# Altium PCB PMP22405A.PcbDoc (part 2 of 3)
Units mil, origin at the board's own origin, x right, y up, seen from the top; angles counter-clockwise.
Board outline 4300 x 4000 mil, 6 copper layers (Top Layer, Layer 2, Signal Layer 3, Signal Layer 4, Layer 5, Bottom Layer), stack 61.712 mil thick; 195 components, 65 nets, 472 pads, 772 vias.
Unrouted connection lines stored in the file: 12.
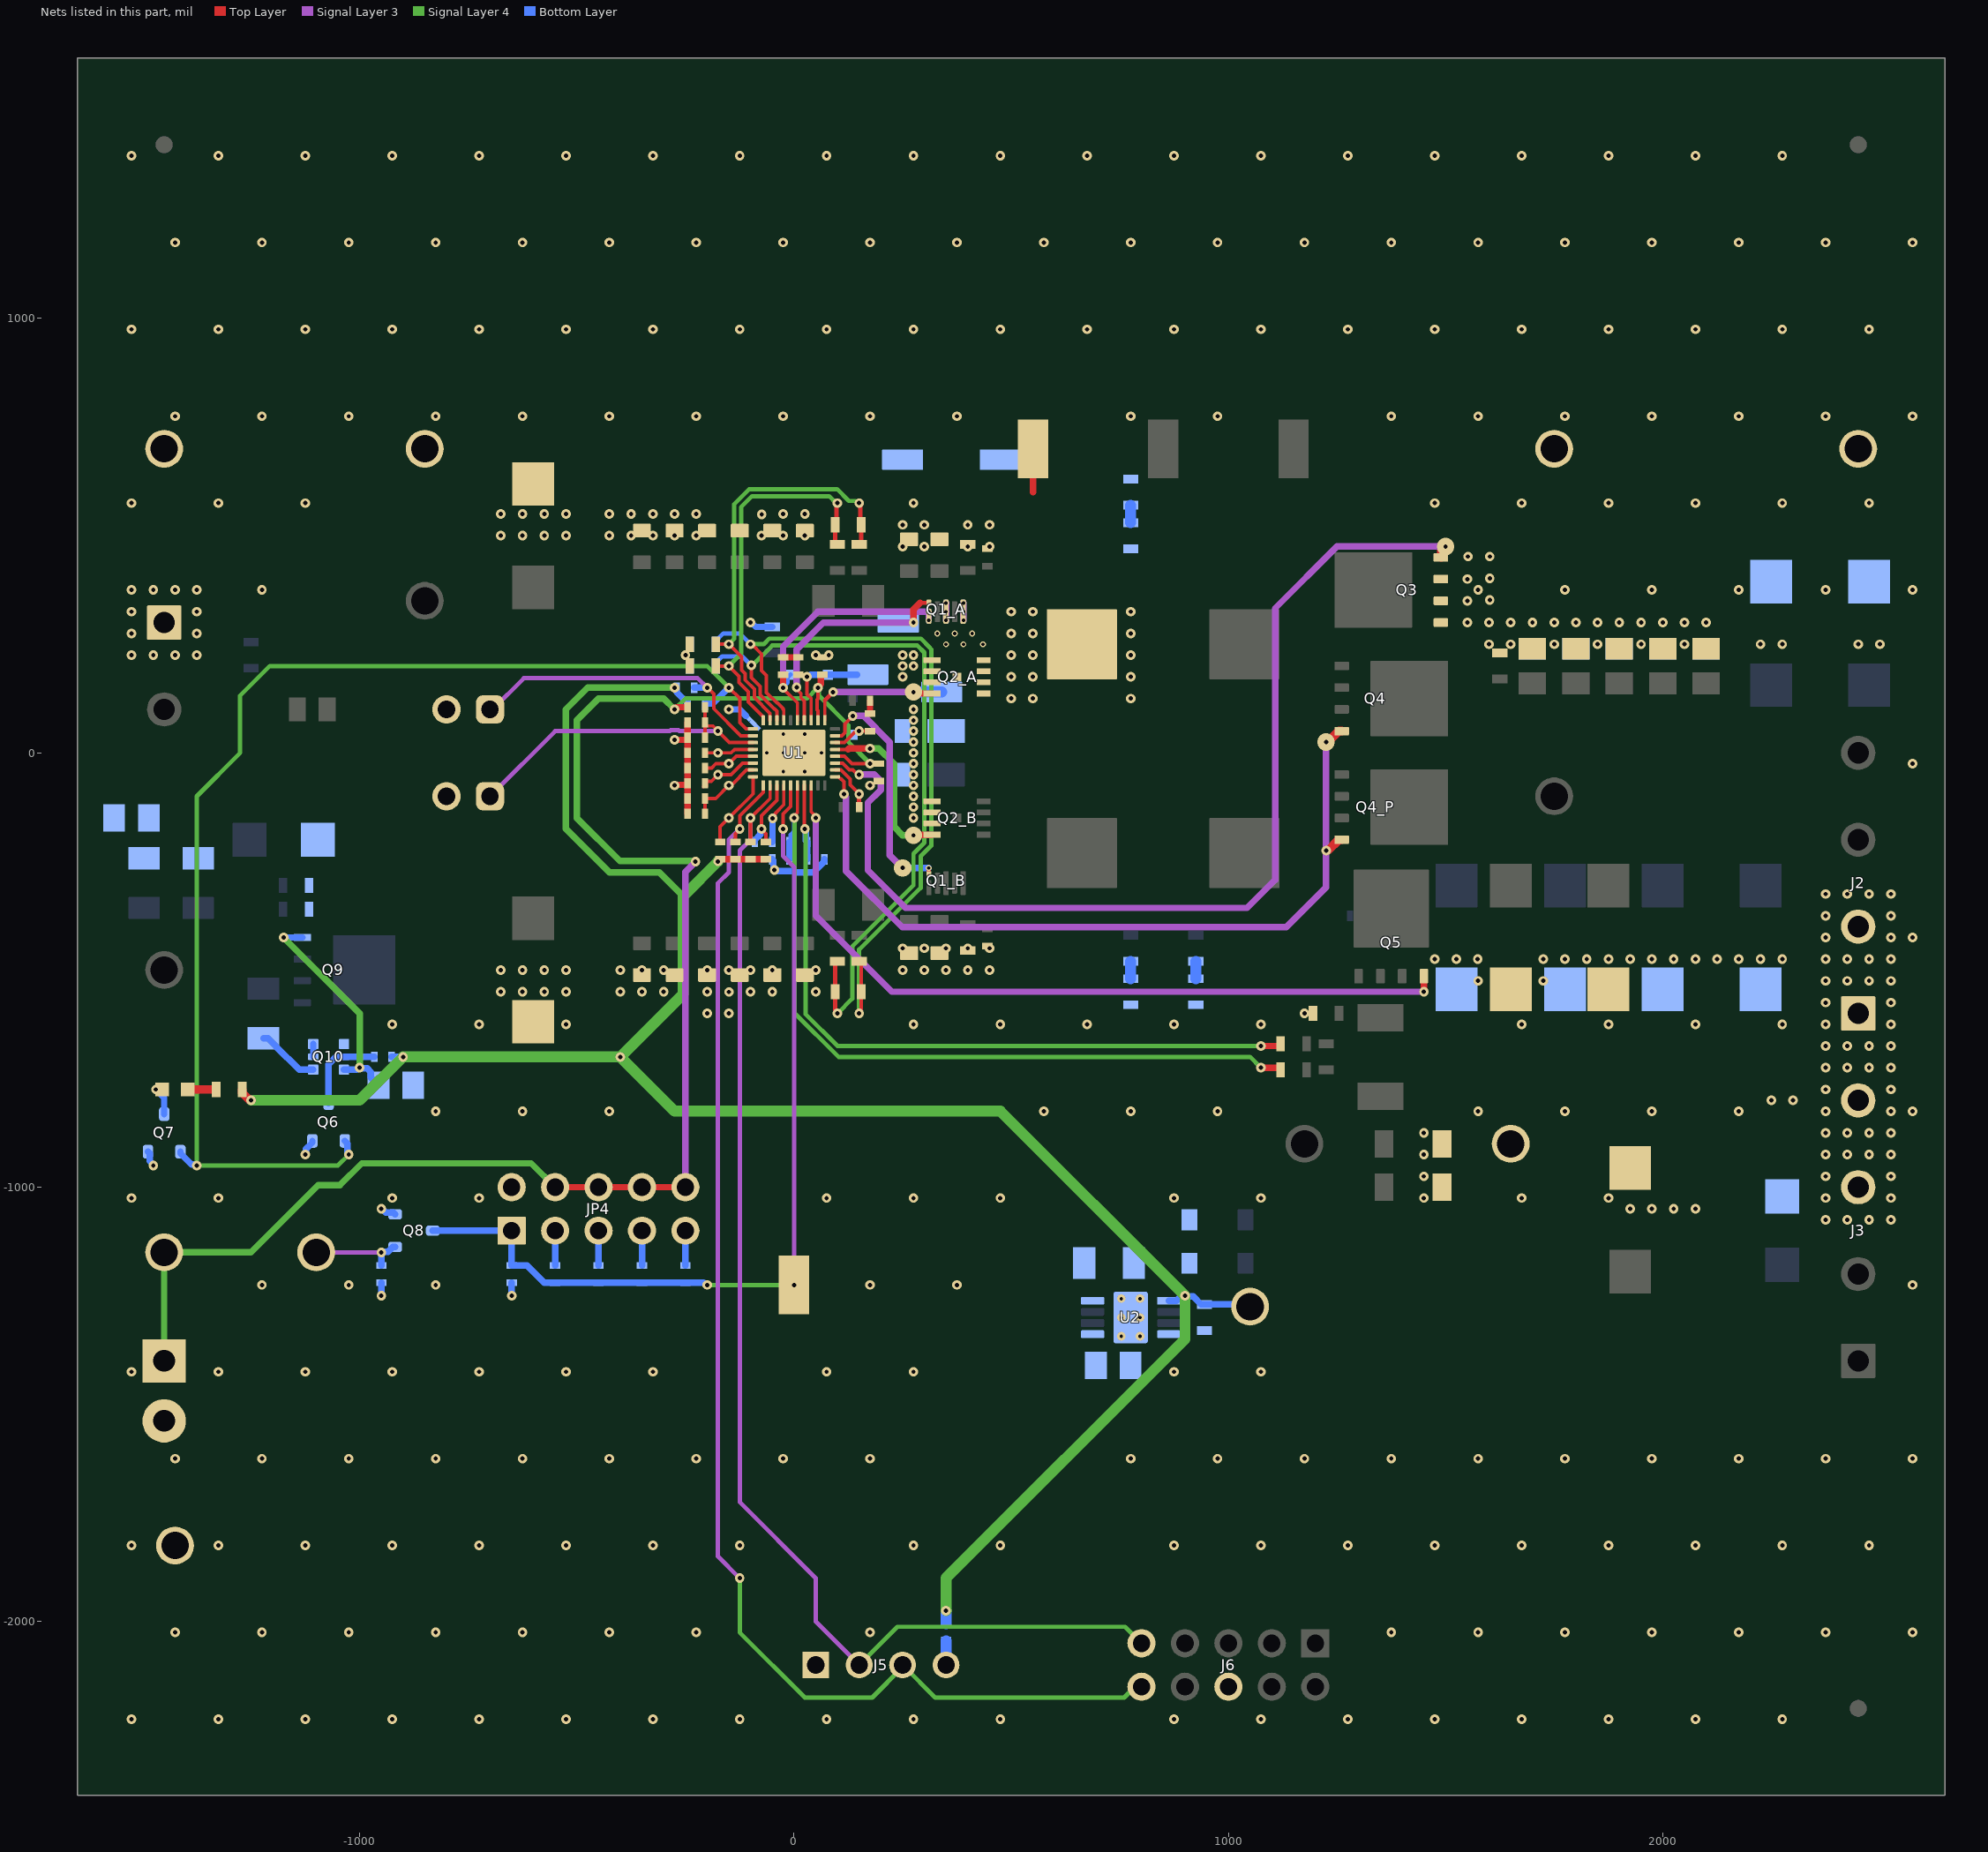
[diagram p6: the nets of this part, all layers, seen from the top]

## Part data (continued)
C51 C60 C62: library part CMP-0007449-4, "CAP, CERM, 330 pF, 50 V, +/- 10%, X7R, 0603", Cap_Case=0603, Manufacturer=MuRata, PartNumber=GRM188R71H331KA01D, Supplier Part Number 1=490-1486-1-ND, TempCo=X7R, Tolerance_%=10%, Value1=Unknown, Value2=50V, ValueDisplayed=330pF
C52: library part CMP-0077895-3, "CAP, CERM, 0.22 µF, 100 V,+/- 20%, X7S, AEC-Q200 Grade 1, 0603", Cap_Case=0603, Manufacturer="Taiyo Yuden", Supplier Part Number 1=587-5013-1-ND, TempCo=X7S, Tolerance_%=20%, Value2=100V, ValueDisplayed=0.22µF
C61 C72: library part CMP-0750059-1, "CAP, CERM, 1 µF, 100 V,+/- 10%, X7S, 0805", Cap_Case=0805, Manufacturer=TDK, TempCo=X7S, Tolerance_%=10%, Value2=100V, ValueDisplayed=1µF
C63 C65: library part CMP-0006681-2, "CAP, CERM, 0.018 uF, 50 V, +/- 10%, X7R, 0402", Cap_Case=0402, Manufacturer=MuRata, Supplier Part Number 1=GRM155R71H183KA12D-ND, TempCo=X7R, Tolerance_%=10%, Value1=Unknown, Value2=50V, ValueDisplayed=0.018uF
C64: library part CMP-0006331-2, "CAP, CERM, 0.068 uF, 50 V, +/- 10%, X7R, AEC-Q200 Grade 1, 0402", Cap_Case=0402, Manufacturer=TDK, Supplier Part Number 1=445-6898-1-ND, TempCo=X7R, Tolerance_%=10%, Value1="0.05606 ohm", Value2=50V, ValueDisplayed=0.068uF
C71: library part CMP-0007355-6, "CAP, CERM, 10 uF, 35 V, +/- 20%, X5R, 0603", Cap_Case=0603, Manufacturer=Murata, TempCo=X5R, Tolerance_%=20%, Value1=Unknown, Value2=35V, ValueDisplayed=10uF
D1: library part CMP-0002827-3, "LED, Green, SMD", Color=green, Manufacturer=Lite-On, PartNumber=LTST-C190GKT, Power_TotalModule=100mW, Value1=0.1W, Value2=2.1V
D2 D3: library part CMP-0005870-3, "Diode, Zener, 5.1 V, 400 mW, SOD-323F", Manufacturer="Diodes Inc.", Power_W=400mW, Value1=0.4W
D4 D5: library part CMP-0076948-2, "Diode, Schottky, 100 V, 2 A, PowerDI123", Manufacturer="Diodes Inc.", Value1=2A, Value2=0.86V
D6: library part CMP-0028403-2, "Diode, Schottky, 40 V, 2 A, SMA", Manufacturer="Diodes Inc.", Value1=2A, Value2=0.5V
D7 D8: library part CMP-0750148-1, "Diode, Switching, 100 V, 0.3 A, AEC-Q101, SOD-123", Manufacturer="Diodes Inc.", Value1=0.3A, Value2=1.25V
FID1 FID2 FID3 FID4 FID5 FID6: library part CMP-0077181-1, "Fiducial mark.  There is nothing to buy or mount.", Manufacturer=N/A
H3 H4 H5 H6: library part CMP-0003620-1, "Bumpon, Hemisphere, 0.44 X 0.20, Clear", Manufacturer=3M, PartNumber="SJ-5303 (CLEAR)", Supplier Part Number 1=SJ5303-7-ND
J1: library part CMP-0074910-1, "Terminal Block, 5.08 mm, 2x1, Brass, TH", Color=Blue, Current_A=15A, Manufacturer="On-Shore Technology", PartNumber=ED120/2DS, Supplier Part Number 1=ED1609-ND, Voltage_V=300V
J2 J3: library part CMP-0074939-1, "Terminal Block, 5.08 mm, 4x1, Brass, TH", Color=Blue, Current_A=15A, Manufacturer="On-Shore Technology", Supplier Part Number 1=ED2227-ND, Voltage_V=300V
J4: library part CMP-0074913-1, "Terminal Block, 3.5mm Pitch, 2x1, TH", Color=Grey, Current_A=6A, Manufacturer="On-Shore Technology", Supplier Part Number 1=ED1514-ND, Voltage_V=150V
J5: library part CMP-0089047-2, "Connector Header Through Hole, Right Angle 4 position 0.100\" (2.54mm)", Current_A=4A, Manufacturer=Molex, Voltage_V=500V
J6: library part CMP-0055448-2, "Header (shrouded), 100mil, 5x2, High-Temperature, Gold, TH", Manufacturer=3M, Supplier Part Number 1=MHC10K-ND
JP1 JP2: library part CMP-0075405-3, "Header, 100mil, 2x1, Gold, TH", Color=Black, Current_A=6.3A, Manufacturer=Samtec, Supplier Part Number 1=SAM1029-02-ND, Voltage_V=550V
JP4: library part CMP-0075410-2, "Header, 100mil, 5x2, Gold, TH", Color=Black, Current_A=6.3A, Manufacturer=Samtec, Supplier Part Number 1=SAM1028-05-ND, Voltage_V=550V
L1_A L1_B: library part CMP-0089738-2, "Fixed Inductor 4.7uH 20% 100kHz 15A 7.5mOhm", Manufacturer=Cyntec, Operating Temperature Range="-55°C to +125°C", Part Number=CMLE105T-4R7MS, Test Frequency=100kHz, Tolerance_%=20%
LBL1: library part CMP-0003625-1, "Thermal Transfer Printable Labels, 0.650\" W x 0.200\" H - 10,000 per roll", Manufacturer=Brady, Supplier Part Number 1=97C5133
LOGO2: library part CMP-0074837-2, "IEC 61010-1 Hot Surface Warning", Manufacturer="Texas Instruments"
Logo3: library part CMP-0074769-3, Manufacturer="Texas Instruments"
LOGO4: library part CMP-0074844-1
Logo5: library part CMP-0074847-1, "FCC_disclaimer"
NT1: library part CMP-0078142-6, "Single point connection between nets.", Manufacturer=N/A
Q1_A Q1_B: library part EPC2204, "100V 32A 6mE", Manufacturer=EPC, Supplier Part Number 1=917-1223-1-ND
Q2_A Q2_B: library part CMP-0084434-1, "MOSFET, N-CH, 80 V, 40 A, 8-PG-TSDSON", Alternate Manufacturer=None, Manufacturer="Infineon Technologies", Value1="0.0135 ohm", Value2="22 nC"
Q3 Q4 Q4_P Q5: library part CMP-0096418-1, "N-Channel 60 V 100A (Tc) 83W (Tc) Surface Mount PG-TDSON-8-7", Digikey Part Number=BSC027N06LS5ATMA1CT-ND, Drain To Source Breakdown Voltage=60V, Input Capacitace At Vds="3300pF @ 30V", Manufacturer=Infineon, Mouser Part Number=726-BSC027N06LS5ATMA, Operating Temperature Range="-55°C to +150°C", Power_W=2.5W, Pulse Drain Current=536A, Typ Forward Diode Voltage=0.8V
Q6 Q7 Q8: library part CMP-0000772-1, "MOSFET, N-CH, 60 V, 0.26 A, SOT-23", Alternate Manufacturer=None, Manufacturer="ON Semiconductor", PartNumber=2N7002ET1G, Supplier Part Number 1=2N7002ET1GOSCT-ND, Value2="0.81 nC"
Q9: library part CMP-0000142-3, "MOSFET, P-CH, -80 V, -32 A, AEC-Q101, PowerPAK_SO-8L", Alternate Manufacturer=None, Manufacturer=Vishay-Siliconix, Value2="101 nC"
Q10: library part CMP-0121666-1, "Pre-Biased Bipolar Transistor (BJT) 1 NPN, 1 PNP - Pre-Biased (Dual) 80V 100mA 170MHz, 150MHz 350mW Surface Mount 6-TSSOP", Collector Base Voltage=80V, Digikey Part Number=1727-NHUMD12XCT-ND, Emitter Base Voltage=10V, Manufacturer=Nexperia, Mouser Part Number=771-NHUMD12X, Operating Temperature Range="to +150°C", Power_W=350mW, Unity Gain Freq=170/150MHz
R1 R2 R15 R16: library part CMP-0022478-4, "RES, 4.99, 1%, 0.1 W, AEC-Q200 Grade 0, 0603", Manufacturer=Vishay-Dale, PartNumber=CRCW06034R99FKEA, Power_W=100mW, Supplier Part Number 1=541-4.99HHCT-ND, TempCo="100 ppm/C", Tolerance_%=1%, Value2=0.1W, Value_Code=4R99, ValueDisplayed=4.99
R3 R6: library part CMP-0026866-3, "RES, 1.0, 5%, 0.063 W, AEC-Q200 Grade 0, 0402", Manufacturer=Vishay-Dale, Power_W=63mW, Supplier Part Number 1=541-1.0JCT-ND, TempCo="200 ppm/C", Tolerance_%=5%, Value2=0.063W, Value_Code=1R00, ValueDisplayed=1.0
R4: library part CMP-0020833-2, "RES, 0, 1%, 0.5 W, 0805", Manufacturer=Keystone, Power_W=500mW, Supplier Part Number 1=36-5106CT-ND, TempCo=ppm/C, Tolerance_%=1%, Value2=0.5W, Value_Code=0
R5: library part CMP-0026158-2, "RES, 200 k, 1%, 0.063 W, AEC-Q200 Grade 0, 0402", Manufacturer=Vishay-Dale, Power_W=63mW, Supplier Part Number 1=541-200KLCT-ND, TempCo="100 ppm/C", Tolerance_%=1%, Value2=0.063W, Value_Code=200k
R7 R26: library part CMP-0026279-2, "RES, 300 k, 1%, 0.063 W, AEC-Q200 Grade 0, 0402", Manufacturer=Vishay-Dale, Power_W=63mW, Supplier Part Number 1=541-300KLCT-ND, TempCo="100 ppm/C", Tolerance_%=1%, Value2=0.063W, Value_Code=300k
R8: library part CMP-0026336-2, "RES, 3.57 k, 1%, 0.063 W, AEC-Q200 Grade 0, 0402", Manufacturer=Vishay-Dale, Power_W=63mW, Supplier Part Number 1=541-3.57KLCT-ND, TempCo="100 ppm/C", Tolerance_%=1%, Value2=0.063W, Value_Code=3k57, ValueDisplayed=3.57k
R9: library part CMP-0026027-3, "RES, 15.0 k, 1%, 0.063 W, AEC-Q200 Grade 0, 0402", Manufacturer=Vishay-Dale, Power_W=63mW, Supplier Part Number 1=541-15.0KLCT-ND, TempCo="100 ppm/C", Tolerance_%=1%, Value2=0.063W, Value_Code=15k0, ValueDisplayed=15.0k
R10: library part CMP-0026744-1, "RES, 82.0 k, 1%, 0.063 W, 0402", Manufacturer="Yageo America", Power_W=63mW, Supplier Part Number 1=311-82.0KLRCT-ND, TempCo="100 ppm/C", Tolerance_%=1%, Value2=0.063W, Value_Code=82k0, ValueDisplayed=82.0k
R11 R12 R13 R14 R24 R48: library part CMP-0025958-3, "RES, 10.0 k, 1%, 0.063 W, AEC-Q200 Grade 0, 0402", Manufacturer=Vishay-Dale, Power_W=63mW, Supplier Part Number 1=541-10.0KLCT-ND, TempCo="100 ppm/C", Tolerance_%=1%, Value2=0.063W, Value_Code=10k0, ValueDisplayed=10.0k
R17 R18: library part CMP-0025703-4, "RES, 10, 5%, 0.1 W, AEC-Q200 Grade 0, 0603", Manufacturer=Vishay-Dale, PartNumber=CRCW060310R0JNEA, Power_W=100mW, Supplier Part Number 1=541-10GCT-ND, TempCo="200 ppm/C", Tolerance_%=5%, Value2=0.1W, Value_Code=10R0, ValueDisplayed=10
R19: library part CMP-0022268-4, "RES, 2.00 k, 1%, 0.1 W, AEC-Q200 Grade 0, 0603", Manufacturer=Vishay-Dale, PartNumber=CRCW06032K00FKEA, Power_W=100mW, Supplier Part Number 1=541-2.00KHCT-ND, TempCo="100 ppm/C", Tolerance_%=1%, Value2=0.1W, Value_Code=2k00, ValueDisplayed=2.00k
R21 R30 R32: library part CMP-0025829-4, "RES, 56, 5%, 0.1 W, AEC-Q200 Grade 0, 0603", Manufacturer=Vishay-Dale, PartNumber=CRCW060356R0JNEA, Power_W=100mW, Supplier Part Number 1=541-56GCT-ND, TempCo="200 ppm/C", Tolerance_%=5%, Value2=0.1W, Value_Code=56R0, ValueDisplayed=56
R23: library part CMP-0026021-3, "RES, 150 k, 1%, 0.063 W, AEC-Q200 Grade 0, 0402", Manufacturer=Vishay-Dale, Power_W=63mW, Supplier Part Number 1=541-150KLCT-ND, TempCo="100 ppm/C", Tolerance_%=1%, Value2=0.063W, Value_Code=150k
R25: library part CMP-0026721-1, "RES, 100 k, 1%, 0.0625 W, 0402", Manufacturer="Yageo America", Power_W=62.5mW, Supplier Part Number 1=311-100KLRCT-ND, TempCo="100 ppm/C", Tolerance_%=1%, Value2=0.0625W, Value_Code=100k
R27: library part CMP-0025958-3, "RES, 10.0 k, 1%, 0.063 W, AEC-Q200 Grade 0, 0402", Manufacturer=Vishay-Dale, PartNumber=CRCW040210K0FKED, Power_W=63mW, Supplier Part Number 1=541-10.0KLCT-ND, TempCo="100 ppm/C", Tolerance_%=1%, Value2=0.063W, Value_Code=10k0, ValueDisplayed=10.0k
R28: library part CMP-0078584-1, "RES, 33.0 k, 1%, 0.063 W, 0402", Manufacturer="Yageo America", Power_W=63mW, Supplier Part Number 1=311-33.0KLRCT-ND, TempCo="100 ppm/C", Tolerance_%=1%, Value2=0.063W, Value_Code=33k0, ValueDisplayed=33.0k
R29: library part CMP-0026071-3, "RES, 1.00 k, 1%, 0.063 W, AEC-Q200 Grade 0, 0402", Manufacturer=Vishay-Dale, Power_W=63mW, Supplier Part Number 1=541-1.00KLCT-ND, TempCo="100 ppm/C", Tolerance_%=1%, Value2=0.063W, Value_Code=1k00, ValueDisplayed=1.00k
R33: library part CMP-0026893-2, "RES, 2.0 M, 5%, 0.063 W, AEC-Q200 Grade 0, 0402", Manufacturer=Vishay-Dale, Power_W=63mW, Supplier Part Number 1=541-2.0MJCT-ND, TempCo="200 ppm/C", Tolerance_%=5%, Value2=0.063W, Value_Code=2M00, ValueDisplayed=2.0M
R34 R35: library part CMP-0018679-3, "RES, 3.9, 5%, 0.25 W, AEC-Q200 Grade 0, 1206", Manufacturer=Vishay-Dale, PartNumber=CRCW12063R90JNEA, Power_W=250mW, Supplier Part Number 1=541-3.9ECT-ND, TempCo="200 ppm/C", Tolerance_%=5%, Value2=0.25W, Value_Code=3R90
R44: library part CMP-0022735-5, "RES, 100 k, 1%, 0.1 W, 0603", Manufacturer=Yageo, Power_W=100mW, Supplier Part Number 1=311-100KHRCT-ND, TempCo="100 ppm/C", Tolerance_%=1%, Value2=0.1W, Value_Code=100k
R45: library part CMP-0026822-3, "RES, 0, 5%, 0.063 W, AEC-Q200 Grade 0, 0402", Manufacturer=Vishay-Dale, Power_W=63mW, Supplier Part Number 1=541-0.0JCT-ND, TempCo="200 ppm/C", Tolerance_%=5%, Value2=0.063W, Value_Code=0000, ValueDisplayed=0
R46 R50: library part CMP-0017299-3, "RES, 10.0, 1%, 0.25 W, AEC-Q200 Grade 0, 1206", Manufacturer=Panasonic, Power_W=250mW, Supplier Part Number 1=P10.0FCT-ND, TempCo="100 ppm/C", Tolerance_%=1%, Value2=0.25W, Value_Code=10R0, ValueDisplayed=10.0
R47: library part CMP-0025743-4, "RES, 1.0, 5%, 0.1 W, AEC-Q200 Grade 0, 0603", Manufacturer=Vishay-Dale, Power_W=100mW, Supplier Part Number 1=541-1.0GCT-ND, TempCo="200 ppm/C", Tolerance_%=5%, Value2=0.1W, Value_Code=1R00, ValueDisplayed=1.0
R49: library part CMP-0021042-3, "RES, 20.0 k, 1%, 0.125 W, AEC-Q200 Grade 0, 0805", Manufacturer=Vishay-Dale, Power_W=125mW, Supplier Part Number 1=541-20.0KCCT-ND, TempCo="100 ppm/C", Tolerance_%=1%, Value2=0.125W, Value_Code=20k0, ValueDisplayed=20.0k
R51: library part CMP-0092287-1, "100 ±5% 0.063W, 1/16W Chip Resistor 0402 (1005 Metric) Moisture Resistant Thick Film", Digikey Part Number=13-RC0402JR-13100RLTR-ND, Manufacturer=Yageo, Mouser Part Number=603-RC0402JR-13100RL, Operating Temperature Range="-55°C to +155°C", Power_W=63mW, TempCo=100ppm/°C, Tolerance_%=5%
RAC_A RAC_B: library part CMP-0018570-2, "RES, 0.01, 1%, 1 W, 1206", Manufacturer=Vishay-Dale, Power_W=1W, Supplier Part Number 1=WSLP-.01CT-ND, TempCo="75 ppm/C", Tolerance_%=1%, Value_Code=R010, ValueDisplayed=0.01
RSR: library part CMP-0016512-2, "RES, 0.005, 1%, 1.5 W, 2010", Manufacturer="Stackpole Electronics Inc", Power_W=1.5W, Supplier Part Number 1=CSNL2010FT5L00CT-ND, TempCo="50 ppm/C", Tolerance_%=1%, Value_Code=5L000, ValueDisplayed=0.005
SH-JP1 SH-JP2 SH-JP4: library part CMP-0003623-3, "Shunt, 100mil, Gold plated, Black", Alternate Manufacturer=3M, Alternate PartNumber=969102-0000-DA, Manufacturer=Samtec, Supplier Part Number 1=SAM8858-ND
TP1 TP22 TP23 TP24 TP29 TP31 TP32: library part CMP-0055147-2, "Test Point, Multipurpose, Red, TH", Color=Red, Manufacturer="Keystone Electronics", Supplier Part Number 1=36-5010-ND
TP2 TP3 TP4 TP11 TP40: library part CMP-0067620-1, "PC Test Point, SMT", Manufacturer="TE Connectivity", Supplier Part Number 1=A106145CT-ND
TP15 TP16 TP17 TP33: library part CMP-0055152-2, "Test Point, Miniature, SMT", Manufacturer="Keystone Electronics", Supplier Part Number 1=36-5015TR-ND
TP18 TP19 TP20 TP21 TP30 TP41: library part CMP-0055148-2, "Test Point, Multipurpose, Black, TH", Color=Black, Manufacturer="Keystone Electronics", Supplier Part Number 1=36-5011-ND
U1: library part CMP-0121663-1, "40-V, SMBus, 2- to 5-Cell, Narrow VDC Quasi Dual Phase Buck-Boost Battery Charge Controller With System Power Monitor and Processor Hot Monitor", Manufacturer="Texas Instruments", Max Supply Voltage=40V, Min Supply Voltage=3.5V, Operating Temperature Range=to
U2: library part CMP-0035936-3, "60V, 5uA IQ Low-Dropout 100mA Linear Regulator with Enable and Power Good, DGN0008C (VSSOP-8)", Alternate Manufacturer="Texas Instruments", Alternate PartNumber=TPS7A1633DGNT, Power Good=TRUE, Rating=Catalog
Z1: library part CMP-0084947-1, "Diode, TVS, Uni, 10 V, 17 Vc, 400 W, 23.5 A, SMA", Manufacturer=Littelfuse, Value1=17V
ZZ1: library part CMP-0003616-3
ZZ2: library part CMP-0077236-1, Alternate Manufacturer=-
ZZ3: library part CMP-0077237-1, Alternate Manufacturer=-
ZZ4: library part CMP-0077238-1, Alternate Manufacturer=-

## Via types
v1: diameter 22, hole 10, Top Layer to Bottom Layer, tented both sides, 723 vias
v2: diameter 13.8, hole 7.8, Top Layer to Bottom Layer, tented both sides, 29 vias
v3: diameter 19.68, hole 7.87, Top Layer to Bottom Layer, tented both sides, 14 vias
v4: diameter 22/22/22/40 (per signal layer), hole 10, Top Layer to Bottom Layer, tented top, 6 vias

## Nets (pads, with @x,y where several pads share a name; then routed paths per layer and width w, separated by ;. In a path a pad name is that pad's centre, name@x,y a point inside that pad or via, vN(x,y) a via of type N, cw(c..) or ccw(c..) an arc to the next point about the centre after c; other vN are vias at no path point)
3V3: C71.2 R11.1 R12.2 R13.2 R14.2 R19.2 R24.2 R27.1 R48.2 R51.1 TP31.1 U2.1 | length 5231.2
  Top Layer w15: v1(-175,-250) R11.1@-170,-245 R12.2@-135,-245 R13.2@-100,-245 R14.2@-65,-245
  Top Layer w20: R19.2@-1270,-775 -1270,-782.5 -1253.84,-798.66 -1251.34,-798.66 v1(-1250,-800)
  Signal Layer 4 w15: v1(-275,150) -475,150 -525,100 -525,-175 -425,-275 -310,-275 -255,-330
  Signal Layer 4 w25: v1(-1250,-800) -1000,-800 v1(-900,-700) v1(-400,-700) ; v1(-175,-250) -255,-330 -255,-555 v1(-400,-700) ; v1(350,-1975) 350,-1900 900,-1350 v1(900,-1250) 475,-825 -275,-825 v1(-400,-700)
  Bottom Layer w15: R48.2@-926.39,-700 v1(-900,-700) ; R24.2@-270,139.5 -245,114.5 R27.1@-245,110 ; U2.1@862.6,-1261.61 880.31,-1261.61 v1@890.59,-1251.34 ; v1(900,-1250) 901.34,-1251.34 918.84,-1251.34 937.5,-1270 1045,-1270 TP31.1@1050,-1275
  Bottom Layer w25: R51.1@350,-2005.32 v1(350,-1975)
ACN_A: C2.2 C19.1 R2.1 U1.9 | length 979.3
  Top Layer w8: C19.1@-180,250 v1(-150,250) -120.88,220.88 -120.88,190.68 -112.38,182.18 -112.38,167.58 -91.49,146.69 -91.49,127.39 -55.18,91.09 -55.18,74.87 U1.9@-55.12,74.8
  Top Layer w10: R2.1@150,480 155,485 C2.2@155,525 152.3,527.7 v1@152.3,572.7
  Top Layer w15: v1@152.3,572.7 v1(150,575) v1@152.3,577.3
  Signal Layer 4 w10: v1(-150,250) -138,262 -138,572 -103,607 99.11,607 126.11,580 v1@141.75,580
ACN_B: C43.2 C58.1 R16.1 U1.7 | length 1777.3
  Top Layer w8: v1(-100,250) -97.56,250 -75,227.44 -75,189.7 -63.49,178.19 -63.49,138.99 -39.5,115 -38.26,115 -25.37,102.11 -25.37,100.37 -23.62,98.62 U1.7@-23.62,74.8 ; v1@150,-596.21 155,-591.21 C43.2@155,-550 155,-485 R16.1@150,-480
  Top Layer w15: v1(150,-600) v1@150,-596.21
  Signal Layer 4 w10: v1(-100,250) -69.8,250 -56.8,263 292,263 312.1,242.9 312.1,242.59 316,238.69 316,-213.69 291.5,-238.19 291.5,-311.13 150,-452.63 v1(150,-600)
  Bottom Layer w10: C58.1@-180,250 -180,257.5 -162.5,275 -125,275 v1(-100,250)
ACP_A: C2.1 C22.1 R1.1 U1.10 | length 903.3
  Top Layer w8: C22.1@-180,200 v1(-150,200) -126.38,176.38 -126.38,161.78 -105.49,140.89 -105.49,117.17 -70.87,82.55 U1.10@-70.87,74.8
  Top Layer w10: v1@97.7,572.7 97.7,527.7 C2.1@95,525 95,485 R1.1@100,480
  Top Layer w15: v1@97.7,572.7 v1(100,575)
  Signal Layer 4 w10: v1(-150,200) -122,228 -122,565.37 -96.37,591 75,591 80.75,591 96.75,575 v1(100,575)
ACP_B: C43.1 C59.1 R15.1 U1.8 | length 1718.2
  Top Layer w8: v1(-98.38,201.62) -98.38,173.38 -77.49,152.49 -77.49,133.19 -45.3,101 -44.06,101 -39.37,96.31 U1.8@-39.37,74.8
  Top Layer w10: v1@100,-596.75 95,-591.75 C43.1@95,-550 95,-485 R15.1@100,-480
  Top Layer w15: v1(100,-600) v1@100,-596.75
  Signal Layer 3 w10: v1@-98.94,202.18 v1(-98.38,201.62)
  Signal Layer 4 w10: v1(-98.38,201.62) -95.55,201.62 -50.17,247 284.11,247 300,231.11 300,-207.06 275,-232.06 275,-305 134,-446 134,-566 v1(100,-600)
  Bottom Layer w10: C59.1@-180,200 -180,207.5 -165.5,222 -118.76,222 v1(-98.38,201.62)
BATDRV: Q5.4 U1.26 | length 1812
  Top Layer w8: U1.26@39.37,-74.8 39.37,-135.58 50,-146.21 v1(50,-150)
  Top Layer w15: v1(1450,-550) Q5.4@1450,-514.17
  Signal Layer 3 w15: v1@50,-150.92 50,-375 225,-550 v1(1450,-550)
BTST1_A: C20.1 D2.1 TP4.1 U1.3 | length 246.1
  Top Layer w8: C20.1@10,180 12.5,177.5 27.5,177.5 v1(30,175) 30,135 39.37,125.63 39.37,97.82 U1.3@39.37,74.8
  Signal Layer 3 w10: v1@28,177 v1(30,175)
  Bottom Layer w15: v1(30,175) 33.25,175 38.29,180.04 D2.1@78.35,180.04 ; D2.1@78.37,180.02 129.98,180 TP4.1@145,180
BTST1_B: C24.1 D3.1 U1.34 | length 79.9
  Top Layer w8: U1.34@94.49,23.62 115.92,23.62 v1@139.62,47.32 ; v1(150,50) C24.1@175,50
BTST2: C29.1 U1.30 | length 119.1
  Top Layer w8: U1.30@94.49,-39.37 94.55,-39.43 107.75,-39.43 129,-60.68 129,-73.5 145.25,-89.75 150,-89.75 v1(150,-95)
  Top Layer w10: C29.1@150,-125 v1(150,-95)
CELL_BATPRESZ: JP4.1 Q8.3 R10.1 R23.1 R25.2 R28.1 R29.1 TP33.1 U1.23 | length 2098
  Top Layer w8: v1(-25,-175) -25,-140.74 -7.87,-123.61 U1.23@-7.87,-74.8
  Signal Layer 3 w10: v1(-25,-175) -25,-237.67 0,-262.67 v1(0,-1225)
  Signal Layer 4 w10: v1(-200,-1225) v1(0,-1225)
  Bottom Layer w15: Q8.3@-831.69,-1100 JP4.1@-650,-1100 R25.2@-650,-1180 -615,-1180 -575,-1220 R23.1@-550,-1220 R10.1@-450,-1220 R28.1@-350,-1220 R29.1@-250,-1220 -208.79,-1220 -203.79,-1225 v1(-200,-1225)
CELL_CONTROL: Q8.1 R26.2 TP1.1 | length 216.9
  Signal Layer 3 w10: TP1.1@-1100,-1150 v1(-950,-1150)
  Bottom Layer w15: R26.2@-950,-1180 v1(-950,-1150) -948.73,-1148.73 -934.61,-1148.73 -923.28,-1137.4 Q8.1@-918.31,-1137.4
CHRG_OK: Q6.1 Q7.1 R27.2 U1.11 | length 2946.5
  Top Layer w8: v1(-150,150) -125,125 -125,70 -110.12,55.12 U1.11@-94.49,55.12
  Signal Layer 4 w10: v1(-1025,-925) -1050,-950 v1(-1375,-950) -1375,-100 -1275,0 -1275,131.84 -1206.84,200 -1175,200 -200,200 v1(-150,150)
  Bottom Layer w15: Q7.1@-1412.6,-918.31 -1412.6,-922.24 -1387.14,-947.7 -1377.3,-947.7 v1(-1375,-950) ; Q6.1@-1033.99,-893.31 -1027.74,-899.56 -1027.74,-919.02 -1025,-921.75 v1(-1025,-925) ; R27.2@-205,110 -205,113.16 -186.84,113.16 v1(-150,150)
CMPIN_TR: R33.2 U1.22 | length 141.1
  Top Layer w8: v1(-49.09,-150.91) -49.09,-146.31 -42.71,-139.93 -42.71,-138.65 -23.62,-119.56 U1.22@-23.62,-74.8
  Bottom Layer w15: R33.2@-50,-205 -49.55,-204.55 -49.55,-151.36 v1(-49.09,-150.91)
CMPOUT: R14.1 R33.1 U1.21 | length 185.3
  Top Layer w8: R14.1@-65,-205 -65,-186.4 -75,-176.4 v1(-75,-175) -75,-145 -39.37,-109.37 U1.21@-39.37,-74.8
  Bottom Layer w15: R33.1@-90,-205 -90,-200.5 -77.3,-187.8 -77.3,-177.3 v1(-75,-175)
EN_OTG: JP1.1 R24.1 U1.12 | length 740.2
  Top Layer w8: v1(-199.81,150) -185,135.19 -185,101.56 -122.81,39.37 U1.12@-94.49,39.37
  Signal Layer 3 w10: JP1.1@-700,100 -693.92,100 -621.92,172 -221.81,172 v1(-199.81,150)
  Bottom Layer w15: R24.1@-230,150 v1(-199.81,150)
GND: C19.2 C22.2 C25.2 C27.2 C28.2 C52.2 C58.2 C59.2 C63.2 C65.2 C69.2 J5.1 J6.6 JP1.2 JP2.2 JP4.2 NT1.1 Q6.2 Q7.2 Q8.2 R7.2 R8.1 R9.2 R25.1 R26.1 | length 706.1
  Top Layer w15: v1(-275,-75) -273.66,-73.66 R8.1@-245,-73.66 ; v1(-275,30) -247.5,30 C25.2@-245,32.5 ; C69.2@-245,-140 R9.2@-245,-105 R8.1@-245,-73.66 ; R8.1@-245,-70 R8.1@-245,-73.66 ; R7.2@-245,70 C25.2@-245,35 C25.2@-245,32.5 ; R8.1@-245,-73.66 C27.2@-245,0 C25.2@-245,32.5
  Bottom Layer w15: Q7.2@-1487.4,-918.31 -1483.09,-922.62 -1483.09,-940.02 -1475,-948.11 v1(-1475,-950) ; v1(-1125,-925) -1123.66,-923.66 -1123.66,-912.11 -1108.79,-897.24 Q6.2@-1108.79,-893.31 ; v1(-950,-1250) R26.1@-950,-1220 ; v1(-950,-1050) -948.11,-1050 -939.82,-1058.29 -922.62,-1058.29 Q8.2@-918.31,-1062.6 ; v1(-650,-1250) R25.1@-650,-1220 ; v1(-150,100) -125,100 NT1.1@-110.61,85.61 ; v1(-100,300) -98.11,300 -88.11,290 C52.2@-50,290 ; C65.2@-50,-245 -47.5,-247.5 -47.5,-264.25 -45,-266.75 v1(-45,-270) -43,-272 0.87,-272 3.87,-275 44.5,-275 70,-249.5 C63.2@70,-245
  other v1: -250,225
HIDRV1_A: Q1_A.1 TP3.1 U1.4 | length 537.9
  Top Layer w8: v1(5.96,150.71) 5.96,146.92 16,136.88 16,126.62 23.62,119 U1.4@23.62,74.8
  Top Layer w10: 290,345 290.34,345.34 310.27,345.34 Q1_A.1@310.61,345.69
  Top Layer w15: v1(275,300) 275,330 290,345
  Signal Layer 3 w15: v1(5.96,150.71) 5.5,151.17 5.5,237.78 67.72,300 v1(275,300)
HIDRV1_B: Q1_B.1 U1.35 | length 558.2
  Top Layer w8: U1.35@94.49,39.37 109.73,39.37 116.8,46.44 116.8,66.8 v1(135,85)
  Top Layer w10: v2(310,-265) 310.31,-265.31 310.31,-279.01 Q1_B.1@310.61,-279.31
  Signal Layer 3 w15: v1(135,85) 160,85 220.5,24.5 220.5,-235.5 v4(250,-265)
  Bottom Layer w15: v4(250,-265) v2(310,-265)
HIDRV2: Q4.4 Q4_P.4 U1.29 | length 1847.4
  Top Layer w8: U1.29@102.3,-55.18 107.96,-60.84 109.36,-60.84 115,-66.48 v1(115,-95)
  Top Layer w20: v1(1225,-225) 1225.38,-224.62 1229.63,-224.62 1254.25,-200 Q4_P.4@1260.83,-200 ; v4(1225,25) 1225.38,25.38 1229.63,25.38 1254.25,50 Q4.4@1260.83,50
  Signal Layer 3 w15: v1@116.01,-96.01 116.01,-97.91 120,-101.89 120,-272.33 249.17,-401.5 1133.15,-401.5 1225,-309.65 v1(1225,-225) v4(1225,25)
IADPT: C27.1 U1.14 | length 113.8
  Top Layer w8: C27.1@-205,0 v1(-175,0) -145,0 -137.13,7.87 U1.14@-94.49,7.87
IBAT: C28.1 U1.15 | length 121.7
  Top Layer w8: C28.1@-205,-35 -190,-35 -180,-25 v1(-150,-25) -132.87,-7.87 U1.15@-94.49,-7.87
ILIM_HIZ: C25.1 JP2.1 R5.2 R7.1 U1.13 | length 785.2
  Top Layer w8: C25.1@-205,35 R7.1@-205,62 ; R5.2@-205,105 R7.1@-205,70 R7.1@-205,62 ; U1.13@-94.49,23.62 -148.62,23.62 v1(-175,50) -187,62 R7.1@-205,62
  Signal Layer 3 w10: JP2.1@-700,-100 -550,50 -286.11,50 -284.11,52 -265.89,52 -263.89,50 v1(-175,50)
LODRV1_A: Q2_A.4 TP2.1 U1.1 | length 367.4
  Top Layer w8: U1.1@70.87,74.8 70.87,120.87
  Top Layer w10: 70.87,120.87 v1(90,140)
  Top Layer w15: v4(275,140) 276.89,140 280.28,136.61 Q2_A.4@317.91,136.61
  Signal Layer 3 w15: v1(90,140) v4(275,140)
  Bottom Layer w25: v4(275,140) TP2.1@340,140
LODRV1_B: Q2_B.4 U1.33 | length 386.9
  Top Layer w8: U1.33@102.3,7.81 124.85,7.81
  Top Layer w15: 124.85,7.81 127.04,10 v1(175,10) ; v4@273.66,-188.66 v4(275,-190) 275.81,-189.19 317.11,-189.19 Q2_B.4@317.91,-188.39
  Signal Layer 4 w15: v1(175,10) 195,10 230,-25 230,-170 250,-190 v4(275,-190)
LODRV2: Q3.4 U1.31 | length 2446.7
  Top Layer w8: U1.31@94.49,-23.62 94.55,-23.69 111.8,-23.69 127.12,-39 135.21,-39 146.21,-50 v1(150,-50)
  Top Layer w20: Q3.4@1489.17,450 1489.84,450 1490,450.16 1490,465 v4(1500,475) v4@1500,474.46
  Signal Layer 3 w15: v1(150,-50) 184.65,-50 199.5,-64.85 199.5,-85.15 170,-114.65 170,-270 257.04,-357.04 1042.96,-357.04 1107.5,-292.5 1107.5,332.5 1250,475 v4(1500,475)
MODE: R8.2 U1.16 | length 143.2
  Top Layer w8: R8.2@-208.5,-78 -207.75,-77.25 -202.25,-77.25 -202.25,-65.94 -201.5,-65.19 -190.19,-65.19 v1(-175,-50) -145,-50 -118.62,-23.62 U1.16@-94.49,-23.62
NetC20_2: C20.2 R3.2 | length 35
  Top Layer w15: R3.2@-25,220 C20.2@10,220
NetC24_2: C24.2 R6.2 | length 30
  Top Layer w15: C24.2@175,90 R6.2@175,120
NetC51_2: C51.2 R21.2 | length 40
  Bottom Layer w25: C51.2@775,530 R21.2@775,570
NetC60_2: C60.2 R30.2 | length 40
  Bottom Layer w25: R30.2@925,-520 C60.2@925,-480
NetC61_1: C61.1 R34.1 R35.1
NetC62_2: C62.2 R32.2 | length 40
  Bottom Layer w25: R32.2@775,-520 C62.2@775,-480
NetC70_1: C70.1 Q9.4 Q10.3 R44.1 R49.2 Z1.2 | length 520.9
  Signal Layer 4 w15: v1(-1175,-425) -1000,-600 v1(-1000,-725)
  Bottom Layer w15: v1(-1175,-425) Q9.4@-1131.82,-425 ; Q10.3@-1035.96,-729.53 -1006.42,-729.53 -1001.89,-725 v1(-1000,-725) -998.66,-726.34 -982.68,-726.34 -973.89,-735.13 -973.89,-747.5 R49.2@-956.39,-765
NetC72_2: C72.2 R50.1 U2.5 U2.8
NetD1_1: D1.1 R19.1 | length 65.5
  Top Layer w20: D1.1@-1395.47,-775 R19.1@-1330,-775
NetD1_2: D1.2 Q7.3 | length 64.6
  Bottom Layer w15: v1(-1469,-775) -1450,-794 Q7.3@-1450,-831.69
NetD7_1: D7.1 D8.1 R50.2
NetJ5_4: J5.4 R51.2 | length 55.3
  Bottom Layer w25: J5.4@350,-2100 R51.2@350,-2044.68
NetJP4_3: JP4.3 R23.2 | length 80
  Bottom Layer w15: R23.2@-550,-1180 JP4.3@-550,-1100
NetJP4_5: JP4.5 R10.2 | length 80
  Bottom Layer w15: R10.2@-450,-1180 JP4.5@-450,-1100
NetJP4_7: JP4.7 R28.2 | length 80
  Bottom Layer w15: R28.2@-350,-1180 JP4.7@-350,-1100
NetJP4_9: JP4.9 R29.2 | length 80
  Bottom Layer w15: R29.2@-250,-1180 JP4.9@-250,-1100
NetQ6_3: Q6.3 Q10.2 R48.1 | length 201.8
  Bottom Layer w15: Q6.3@-1071.39,-806.69 -1071.39,-716.95 -1054.44,-700 R48.1@-966.39,-700
NetQ10_4: Q10.4 R46.1 | length 145.2
  Bottom Layer w15: R46.1@-1221.39,-657.09 -1210.56,-657.09 -1192.47,-675.18 -1192.47,-676.22 -1139.17,-729.53 Q10.4@-1106.82,-729.53
NetQ10_5: Q10.5 Q10.6 | length 29.5
  Bottom Layer w15: Q10.5@-1106.82,-700 Q10.6@-1106.82,-670.47
PGND: C1.2 C3.1 C4.1 C5.1 C6.1 C7.1 C8.1 C9.1 C10.1 C11.2 C12.2 C13.2 C14.2 C15.2 C16.2 C17.2 C18.2 C21.2 C23.2 C26.1 C30.2 C31.2 C32.2 C33.1 C34.1 C35.1 C36.1 C37.1 C38.1 C39.1 C40.1 C41.2 C42.2 C44.2 C46.2 C47.2 C48.2 C49.2 C50.2 C53.2 C54.2 C55.2 C56.2 C57.2 C61.2 C66.2 C67.2 C68.2 C71.1 C72.1 D4.2 D5.2 D6.2 J1.1 J2.1 J2.2 J3.3 J3.4 J4.2 NT1.2 Q2_A.1 Q2_A.2 Q2_A.3 Q2_B.1 Q2_B.2 Q2_B.3 Q3.1 Q3.2 Q3.3 Q10.1 R21.1 R30.1 R32.1 R49.1 TP11.1 TP18.1 TP19.1 TP20.1 TP21.1 TP30.1 TP40.1 TP41.1 U1.37 U2.4 U2.9@775,-1300
  other v1: -1525,-2225 -1325,-2225 -1125,-2225 -925,-2225 -725,-2225 -525,-2225 -325,-2225 -125,-2225 75,-2225 275,-2225 475,-2225 875,-2225 1075,-2225 1275,-2225 1475,-2225 1675,-2225 1875,-2225 2075,-2225 2275,-2225 -1425,-2025 -1225,-2025 -1025,-2025 -825,-2025 -625,-2025 -425,-2025 -225,-2025 175,-2025 1375,-2025 1575,-2025 1775,-2025 1975,-2025 2175,-2025 2375,-2025 2575,-2025 -1525,-1825 -1325,-1825 -1125,-1825 -925,-1825 -725,-1825 -525,-1825 -325,-1825 -125,-1825 275,-1825 475,-1825 875,-1825 1075,-1825 1275,-1825 1475,-1825 1675,-1825 1875,-1825 2075,-1825 2275,-1825 2475,-1825 -1425,-1625 -1225,-1625 -1025,-1625 -825,-1625 -625,-1625 -425,-1625 -225,-1625 -25,-1625 175,-1625 775,-1625 975,-1625 1175,-1625 1375,-1625 1575,-1625 1775,-1625 1975,-1625 2175,-1625 2375,-1625 2575,-1625 -1525,-1425 -1325,-1425 -1125,-1425 -925,-1425 -725,-1425 -525,-1425 -325,-1425 75,-1425 275,-1425 875,-1425 1075,-1425 -1225,-1225 -1025,-1225 -825,-1225 175,-1225 375,-1225 2575,-1225 2375,-1075 2425,-1075 2475,-1075 2525,-1075 1925,-1050 1975,-1050 2025,-1050 2075,-1050 -1525,-1025 -1325,-1025 -925,-1025 -725,-1025 75,-1025 275,-1025 475,-1025 875,-1025 1075,-1025 1450,-1025 1675,-1025 1875,-1025 2375,-1025 2525,-1025 1450,-975 2375,-975 2525,-975 1450,-925 2375,-925 2425,-925 2475,-925 2525,-925 1450,-875 2375,-875 2425,-875 2475,-875 2525,-875 -825,-825 -625,-825 -425,-825 575,-825 775,-825 975,-825 1575,-825 1775,-825 1975,-825 2175,-825 2375,-825 2525,-825 2575,-825 2250,-800 2300,-800 2375,-775 2525,-775 2375,-725 2425,-725 2475,-725 2525,-725 2375,-675 2425,-675 2475,-675 2525,-675 -925,-625 -725,-625 -525,-625 275,-625 475,-625 675,-625 875,-625 1075,-625 1675,-625 1875,-625 2075,-625 2275,-625 2375,-625 2525,-625 -200,-600 -150,-600 1175,-600 2375,-575 2525,-575 -149.65,-550.55 -675,-550 -625,-550 -575,-550 -525,-550 -400,-550 -350,-550 -300,-550 -200,-550 -100,-550 -50,-550 50,-550 1575,-525 1725,-525 2375,-525 2425,-525 2475,-525 2525,-525 -675,-500 -625,-500 -575,-500 -525,-500 -400,-500 -350,-500 -300,-500 -200,-500 -150,-500 -100,-500 -50,-500 50,-500 250,-500 300,-500 350,-500 400,-500 450,-500 1475,-475 1525,-475 1574,-475 1725,-475 1775,-475 1825,-475 1875,-475 1925,-475 1975,-475 2025,-475 2075,-475 2125,-475 2175,-475 2225,-475 2275,-475 2375,-475 2425,-475 2475,-475 2525,-475 250,-450 300,-450 350,-450 400,-450 450,-450 2375,-425 2525,-425 2575,-425 2375,-375 2525,-375 2375,-325 2425,-325 2475,-325 2525,-325 275,-150 275,-125 275,-100 175,-75 275,-75 275,-50 275,-25 2575,-25 275,0 275,25 275,50 275,75 275,100 250,175 250,200 275,200 -1525,225 -1475,225 -1425,225 -1375,225 50,225 80,225 250,225 275,225 1600,250 1650,250 1750,250 1850,250 1950,250 2050,250 2225,250 2275,250 2450,250 2500,250 -1525,275 -1375,275 1550,300 1600,300 1650,300 1700,300 1750,300 1800,300 1850,300 1900,300 1950,300 2000,300 2050,300 2100,300 -1525,325 -1375,325 1550,350 1601.65,351.99 -1525,375 -1475,375 -1425,375 -1375,375 -1225,375 1575,375 1775,375 1975,375 2175,375 2375,375 2575,375 1550,400 1601.65,401.99 1551.65,451.99 1601.65,451.99 250,475 300,475 400,475 450,475 -675,500 -625,500 -575,500 -525,500 -425,500 -375,500 -325,500 -275,500 -225,500 -75,500 -25,500 25,500 250,525 300,525 400,525 450,525 -74.42,548.81 -675,550 -625,550 -575,550 -525,550 -425,550 -375,550 -325,550 -275,550 -225,550 -25,550 25,550 -1525,575 -1325,575 -1125,575 275,575 1475,575 1675,575 1875,575 2075,575 2275,575 2475,575 -1425,775 -1225,775 -1025,775 -825,775 -625,775 -425,775 -225,775 -25,775 175,775 375,775 775,775 975,775 1375,775 1575,775 1775,775 1975,775 2175,775 2375,775 2575,775 -1525,975 -1325,975 -1125,975 -925,975 -725,975 -525,975 -325,975 -125,975 75,975 275,975 475,975 675,975 875,975 1075,975 1275,975 1475,975 1675,975 1875,975 2075,975 2275,975 2475,975 -1425,1175 -1225,1175 -1025,1175 -825,1175 -625,1175 -425,1175 -225,1175 -25,1175 175,1175 375,1175 575,1175 775,1175 975,1175 1175,1175 1375,1175 1575,1175 1775,1175 1975,1175 2175,1175 2375,1175 2575,1175 -1525,1375 -1325,1375 -1125,1375 -925,1375 -725,1375 -525,1375 -325,1375 -125,1375 75,1375 275,1375 475,1375 675,1375 875,1375 1075,1375 1275,1375 1475,1375 1675,1375 1875,1375 2075,1375 2275,1375
  other v3: 753.35,-1343.31 796.65,-1343.31 753.35,-1300 796.65,-1300 753.35,-1256.69 796.65,-1256.69 -24.61,-43.31 24.61,-43.31 -62.99,0 -24.61,0 24.61,0 62.99,0 -24.61,43.31 24.61,43.31
PROCHOT: R11.2 U1.18 | length 181.2
  Top Layer w8: R11.2@-170,-205 -170,-170 v1(-150,-150) -94.49,-94.49 U1.18@-94.49,-55.12
PSYS: C69.1 R9.1 U1.17 | length 172.7
  Top Layer w8: C69.1@-205,-140 R9.1@-205,-105 -180,-105 v1(-150,-75) -147.32,-72.32 -142.32,-72.32 -109.37,-39.37 U1.17@-94.49,-39.37
REGN: C23.1 C26.2 J4.1 JP4.4 JP4.6 JP4.8 JP4.10 R5.1 TP32.1 U1.2 U1.32 | length 3940.6
  Top Layer w8: U1.2@55.12,74.8 55.12,96.87 53.37,98.62 53.37,122.7 55.12,124.45 v1@55.12,150 ; U1.32@94.49,-7.87 115.79,-7.87 132.92,-25 v1(175,-25)
  Top Layer w10: v1(175,-25) C26.2@195,-25
  Top Layer w15: JP4.4@-550,-1000 JP4.6@-450,-1000 JP4.8@-350,-1000 JP4.10@-250,-1000 ; v1(-275,100) -270,105 R5.1@-245,105 ; v1(55,150) 55,151.89 61.87,158.76 61.87,180 C23.1@65,180
  Signal Layer 3 w15: JP4.10@-250,-1000 -250,-274.4 -226.81,-251.21 v1(-226.81,-250.22)
  Signal Layer 4 w10: v1(-275,100) -250,125 30,125 v1(55,150) 57.3,147.7 57.3,131.59 125.55,63.34 125.55,24.45 v1(175,-25)
  Signal Layer 4 w15: J4.1@-1450,-1400 TP32.1@-1450,-1150 -1250,-1150 -1095,-995 -1045,-995 -995,-945 -605,-945 JP4.4@-550,-1000 ; v1(-275,100) -300,125 -450,125 -500,75 -500,-150 -401,-249 -228.02,-249 v1(-226.81,-250.22)
SCL: J5.2 J6.9 R13.1 U1.20 | length 2922.8
  Top Layer w8: R13.1@-100,-205 v1(-100,-150) -55.12,-105.12 U1.20@-55.12,-74.8
  Signal Layer 3 w10: v1@-100,-152.44 -100,-200 -125,-225 -125,-1725 50,-1900 50,-2000 J5.2@150,-2100
  Signal Layer 4 w10: J5.2@150,-2100 238,-2012 762,-2012 J6.9@800,-2050
SDA: J5.3 J6.10 R12.1 U1.19 | length 3102.9
  Top Layer w8: R12.1@-135,-205 -135,-186.4 -125,-176.4 v1(-125,-175) -125,-145 -71.04,-91.04 -71.04,-84.01 -70.93,-83.89 U1.19@-70.93,-82.61
  Signal Layer 3 w10: v1(-125,-1900) -175,-1850 -175,-300 -150,-275 -150,-200 v1(-125,-175)
  Signal Layer 4 w10: v1(-125,-1900) -125,-2025 25,-2175 180.01,-2175 250,-2105.01 J5.3@250,-2100 252.5,-2102.5 325,-2175 760.13,-2175 785.13,-2150 J6.10@800,-2150
SRN: C64.2 C65.1 R18.1 U1.24 | length 1803.3
  Top Layer w8: v1(0,-150) 0,-145.94 7.87,-138.07 U1.24@7.87,-74.8
  Top Layer w15: v1@1072.7,-727.3 v1(1075,-725) 1115,-725 R18.1@1120,-730
  Signal Layer 4 w10: v1(0,-150) 1,-151 1,-598.63 102.37,-700 1050,-700 v1(1075,-725)
  Bottom Layer w10: C64.2@-10,-205 -7.5,-202.5 -7.5,-188.61 0,-181.11 v1(0,-150)
  Bottom Layer w15: C65.1@-10,-245 C64.2@-10,-205
SRP: C63.1 C64.1 R17.1 U1.25 | length 1727.4
  Top Layer w8: U1.25@23.62,-74.8 23.68,-74.87 23.68,-173.69 v1(25,-175)
  Top Layer w15: v1(1075,-675) 1117.5,-675 1120,-672.5 R17.1@1120,-670
  Signal Layer 4 w10: v1(25,-175) 27,-177 27,-602 100,-675 v1(1075,-675)
  Bottom Layer w15: v1(25,-175) 27.5,-177.5 27.5,-202.5 C64.1@30,-205 C63.1@30,-245
SW1_A: C51.1 D2.2 D4.1 L1_A.1 Q1_A.2 Q1_A.4 Q1_A.6 Q2_A.5 Q2_A.6 Q2_A.7 Q2_A.8 Q2_A.9 R3.1 TP15.1 U1.5 | length 918.9
  Top Layer w8: v1(-25,150) -25,147.83 7.87,114.95 U1.5@7.87,74.8
  Top Layer w15: v1(-25,150) R3.1@-25,180 ; 550,600 TP15.1@550,700
  Signal Layer 3 w15: v1(-25,150) -25,245 55,325 v2(310,325) v2(310,305) ; v2(350,305) v2(350,325) v2(350,345) ; v2(390,305) v2(390,325) v2(390,345)
  Signal Layer 4 w15: v2(310,305) v2(310,325) ; v2(350,305) v2(350,325) v2(350,345) ; v2(390,305) v2(390,325) v2(390,345)
  Bottom Layer w10: v1(-25,150) -25,151.78 -14.92,161.86 -14.92,173.39 D2.2@-8.27,180.04
  other v1: 500,125 550,125 775,125 500,175 550,175 775,175 500,225 550,225 775,225 500,275 550,275 775,275 500,325 550,325 775,325
  other v2: 350,250 390,250 435,250 330,275 370,275 410,275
